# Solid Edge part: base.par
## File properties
Title: Base
Author: Robert a Rhodes jr
Template: Normal.par
Last saved by: Sham
Revision: 17
Application: Solid Edge
Material: aluminum
Accuracy: 0.99
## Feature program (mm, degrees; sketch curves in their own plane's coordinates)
sketch for "unnamed Protrusion 1" plane through (0, 0, 0) normal (0, 0, 1) x-axis (1, 0, 0)
  line (-85, 25) -> (-85, -25)
  arc centre (-80, -25) radius 5 from (-85, -25) to (-80, -30) ccw
  line (-80, -30) -> (80, -30)
  arc centre (80, -25) radius 5 from (85, -25) to (80, -30) cw
  line (85, -25) -> (85, 25)
  arc centre (80, 25) radius 5 from (80, 30) to (85, 25) cw
  line (80, 30) -> (-80, 30)
  arc centre (-80, 25) radius 5 from (-85, 25) to (-80, 30) cw
extrude "unnamed Protrusion 1" add finite 20 along +normal
sketch for "ExtrudedProtrusion_2" plane through (5, -12, 10) normal (0, -1, 0) x-axis (1, 0, 0)
  line (-50, 10) -> (-50, 50)
  arc centre (15, 50) radius 65 from (-50, 50) to (-20, 104.7723) cw
  line (-20, 104.7723) -> (-20, 144)
  arc centre (-17, 144) radius 3 from (-20, 144) to (-17, 147) cw
  line (-17, 147) -> (37, 147)
  arc centre (37, 144) radius 3 from (37, 147) to (40, 144) cw
  line (40, 144) -> (40, 75)
  line (40, 75) -> (-12, 75)
  line (-12, 28.959) -> (-12, 75)
  line (10, 10) -> (-12, 28.959)
  line (28, 35) -> (10, 10)
  line (40, 35) -> (28, 35)
  line (40, 35) -> (40, 10)
extrude "ExtrudedProtrusion_2" add  Plane_Distance = 18 mm
sketch for "unnamed Cutout 1" plane through (5, -12, 88.5) normal (0, -1, 0) x-axis (1, 0, 0)
  line (-20, -68.5) -> (-20, 4.7281)
  arc centre (-25, 4.7281) radius 5 from (-28.8, 7.9777) to (-20, 4.7281) cw
  arc centre (13, -27.7681) radius 55 from (-42, -27.7681) to (-28.8, 7.9777) cw
  line (-42, -68.5) -> (-42, -27.7681)
  line (-42, -68.5) -> (-20, -68.5)
extrude "unnamed Cutout 1" cut finite 10 along -normal
sketch for "ExtrudedCutout_2" plane through (5, 0, 0) normal (0, 0, -1) x-axis (1, 0, 0)
  line (-10, 1) -> (-10, -19)
  line (-10, -19) -> (30, -19)
  line (30, -19) -> (30, 1)
  line (30, 1) -> (-10, 1)
  dimension (linear) = 10
extrude "ExtrudedCutout_2" cut finite 147 along -normal
sketch for "ExtrudedProtrusion_3" plane through (25, 9, 157) normal (0, 0, 1) x-axis (1, 0, 0)
  circle centre (-10, 0) radius 15
  dimension (linear) = 10
extrude "ExtrudedProtrusion_3" add finite 18 along +normal
sketch for "Hole_1" plane through (25, 9, 175) normal (0, 0, 1) x-axis (1, 0, 0)
  hole centre (-10, 0) bore radius 10
hole "Hole_1" diameter 20 finite
sketch for "Hole_2" plane through (45, 9, 119.9119) normal (1, 0, 0) x-axis (0, 1, 0)
  hole centre (1, 20.0881) bore radius 4
  dimension (linear) = 1
hole "Hole_2" diameter 8 through
mirror "unnamed Mirror 1" of "unnamed Cutout 1" about plane through (5, 9, 88.7059) normal (0, -1, 0)
extrude "unnamed Cutout 2" cut finite 10
fillet "Round_1" radius 3
sketch for "Hole_3" plane through (0, 0, 20) normal (0, 0, 1) x-axis (1, 0, 0)
  hole centre (70, 0) bore radius 6.5
hole "Hole_3" diameter 13 through
sketch for "unnamed Hole 1" plane through (0, 0, 20) normal (0, 0, 1) x-axis (1, 0, 0)
  hole centre (-70, 0) bore radius 6.5
  dimension (linear) = 70
  dimension (linear) = 70
hole "unnamed Hole 1" through
pattern "unnamed Pattern 1" of "Hole_3", "unnamed Hole 1"
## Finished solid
Body 1: solid body, 61 faces, 164 edges, 100 vertices.
  Faces by surface: plane 37, cylinder 23, torus 1
  Edges by curve: line 114, circle 50
Bounding box of the edges (mm; curved faces can reach further): 170.000 x 60.000 x 175.000, from (-85, -30, 0) to (85, 30, 175).
Cylindrical faces by radius (mm): R3 x8, R4 x2, R5 x6, R6.5 x2, R10 x1, R15 x1, R55 x2, R65 x1
Toroidal faces (ring radius, tube radius in mm): R18 r3 x1
Planar faces by outward normal: +x 8, +y 4, +z 5, -x 7, -y 6, -z 4, oblique 3
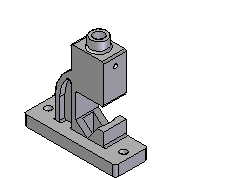
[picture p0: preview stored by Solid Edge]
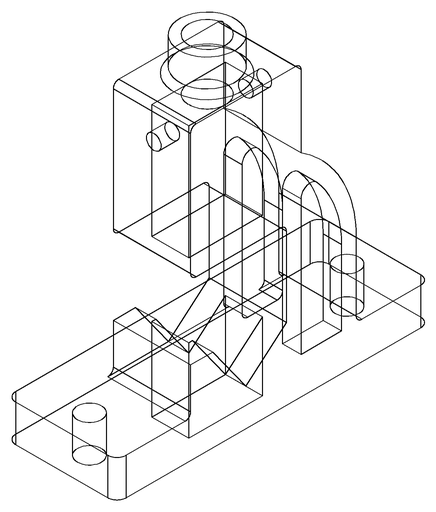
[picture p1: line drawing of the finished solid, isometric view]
